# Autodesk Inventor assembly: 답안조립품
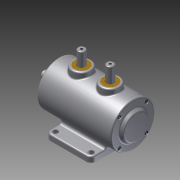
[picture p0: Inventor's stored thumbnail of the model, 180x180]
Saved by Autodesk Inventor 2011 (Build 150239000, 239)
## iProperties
Created: 2014-12
Part Number: 답안조립품
Document SubType Name: Assembly
Designer: user
Author: user
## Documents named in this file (10)
- D:\441225V1012\답안조립품.iam
- D:\441225V1012\본체.ipt
- D:\441225V1012\앞커버.ipt
- D:\441225V1012\오일실.ipt
- D:\441225V1012\축.ipt
- D:\441225V1012\M4-소켓머리.ipt
- D:\441225V1012\뒷커버.ipt
- D:\441225V1012\베어링 6203.ipt
- D:\441225V1012\부시.ipt
- D:\441225V1012\슬라이더.ipt
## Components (11 placed, 3 different names)
1. 8-오일실:2
2. 7-베어링 6203:2
3. 7-베어링 6203:3
4. 9-M4-소켓머리:1
5. 9-M4-소켓머리:13
6. 9-M4-소켓머리:14
7. 9-M4-소켓머리:15
8. 9-M4-소켓머리:2
9. 9-M4-소켓머리:16
10. 9-M4-소켓머리:17
11. 9-M4-소켓머리:18
